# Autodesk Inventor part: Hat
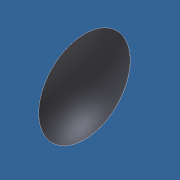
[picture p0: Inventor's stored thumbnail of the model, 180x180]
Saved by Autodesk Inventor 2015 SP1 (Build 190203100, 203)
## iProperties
Category: Mechanical Engineering Drawing and Design - CADD
Manager: Fábio Ricardo de Oliveira Souza
Company: SENAI - Serviço Nacional de Aprendizagem Industrial
Created: 2011-06
Part Number: Hat
Material: Steel
Description: Stainless Steel (DIN- X6CrNiTi18-10)
Document SubType Name: Modeling
Designer: Guilherme Augusto Franco de Souza
Engineer: George Geraldo de Oliveia Silva
Authority: Fábio Ricardo de Oliveira Soza
Density: 7.85 g/cm^3
Mass: 9389.5 g
Surface Area: 23958.4 cm^2
Volume: 1196.11 cm^3
Appearance: Machined 02
Subject: WorldSkill 2011 - London, England
Author: Guilherme Augusto Franco de Souza
Revision Number: 00
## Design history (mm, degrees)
sketch "Sketch2"
  geometry: L1 (-1438.802, 0)-(450.659, 0) reference; A1 r 1313.879 centre (-1168.879, 0) between (145, 0) and (0, 600); 1 further point
  constraints: 2 horizontal alignment, 2 point on circle, 1 centre point, 1 vertical alignment
  dimensions: "d2" = 1200 diameter of A1.end L1; "d4" = 145 distance of A1.start point (0, 0)
feature "RevolutionSrf1" sketch "Sketch2" dims angle "d5" = 90 deg
thicken "Thicken1" dims "d6" = 1, "d7" = 1
body "Solid2"
body "Srf1"
